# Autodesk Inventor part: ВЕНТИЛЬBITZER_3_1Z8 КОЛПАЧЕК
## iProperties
Created: 2011-02
Part Number: ВЕНТИЛЬBITZER_3_1Z8 КОЛПАЧЕК
Document SubType Name: Modeling
Designer: Чернышев Юрий
Mass: 71.9651 g
Surface Area: 104.154 cm^2
Volume: 71.9651 cm^3
Density: 1 g/cm^3
Author: Чернышев Юрий
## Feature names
1. RevolutionAngle1
